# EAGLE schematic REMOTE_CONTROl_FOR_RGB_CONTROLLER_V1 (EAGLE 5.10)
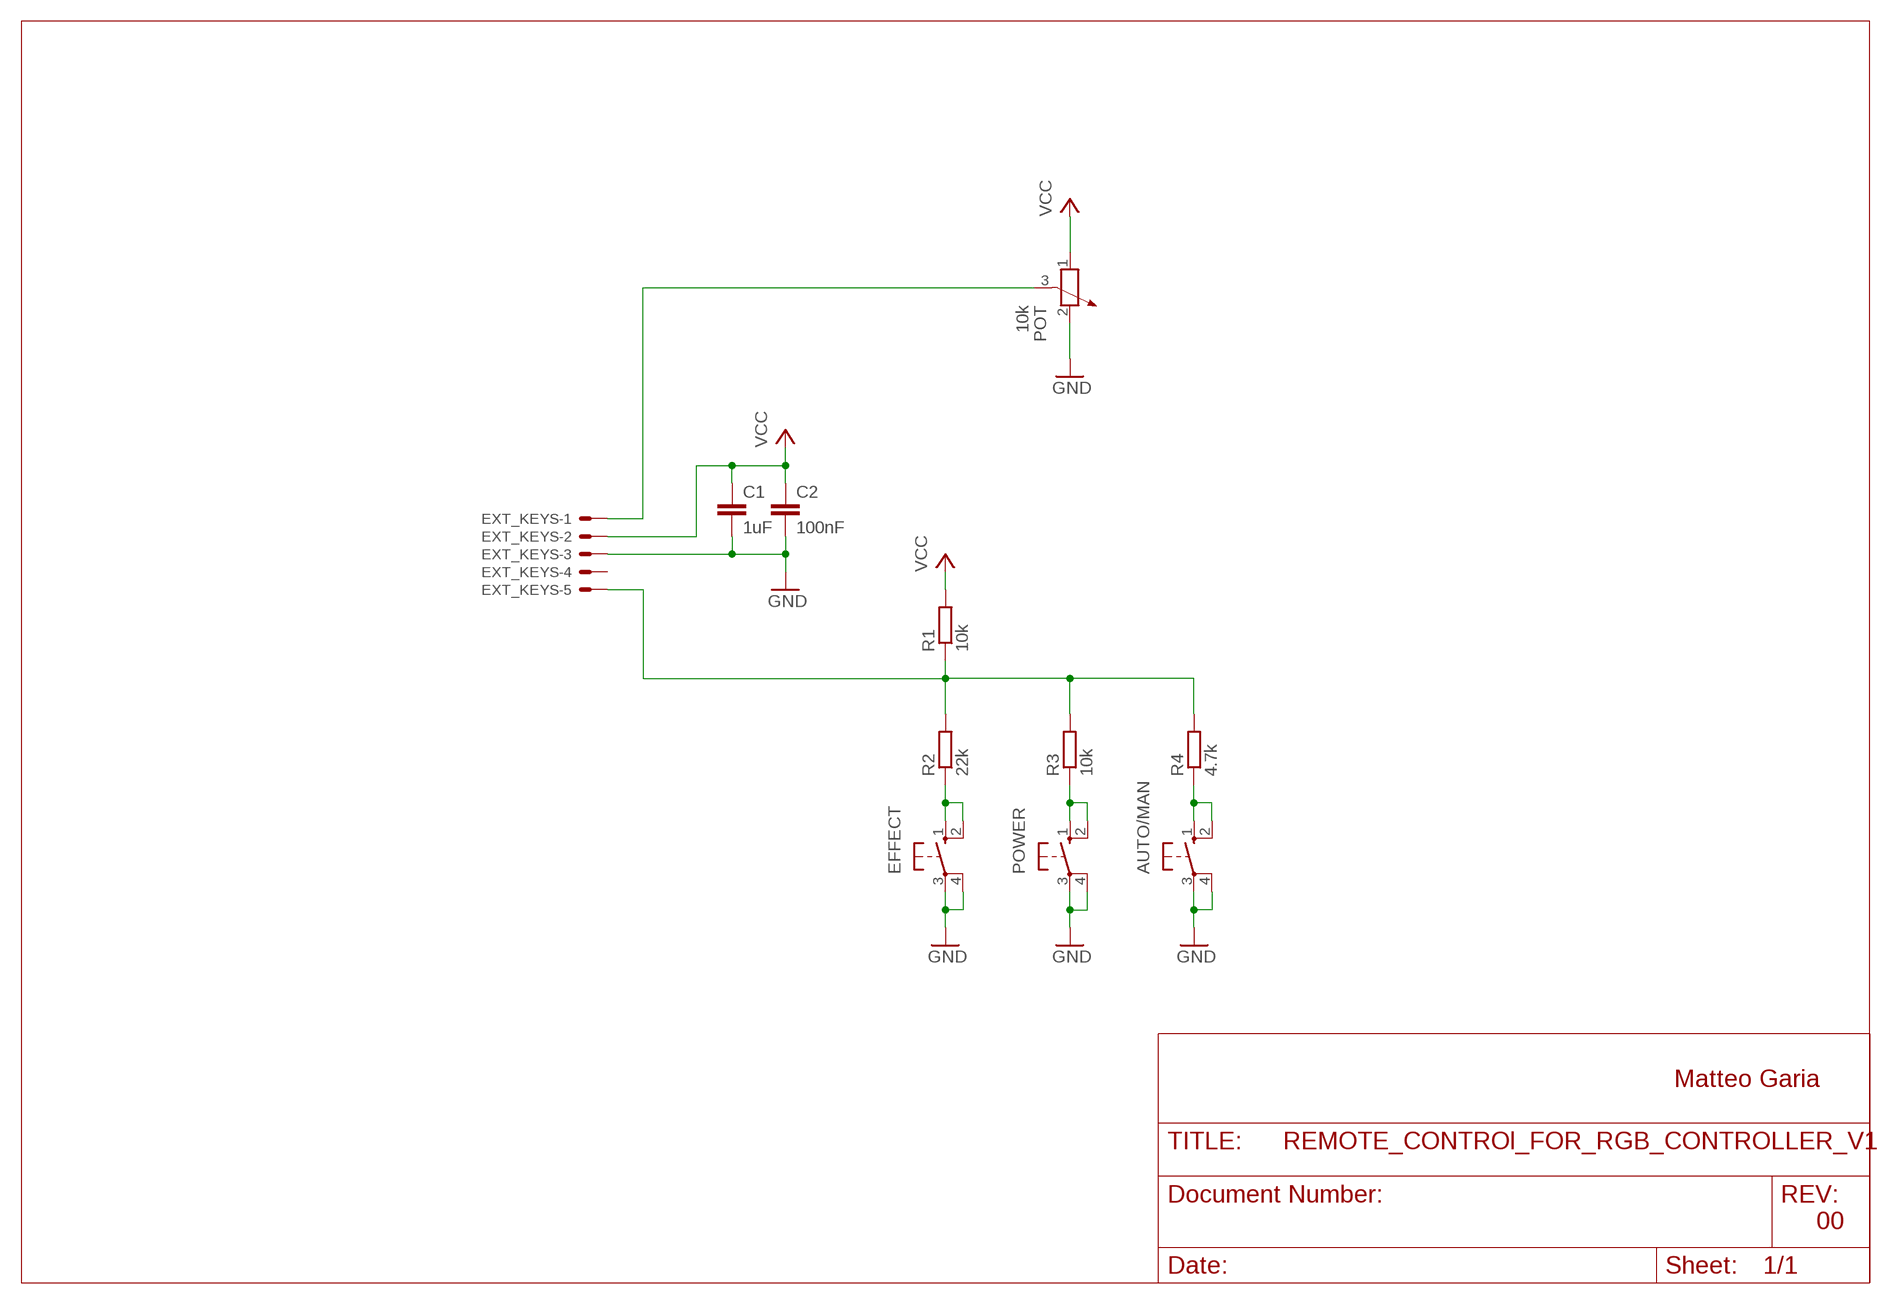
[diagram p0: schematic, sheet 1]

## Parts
AUTO/MAN  10-XX  [B3F-10XX]
C1  1uF  C-EU025-024X044  [C025-024X044]
C2  100nF  C-EU025-024X044  [C025-024X044]
EFFECT  10-XX  [B3F-10XX]
EXT_KEYS  22-23-2051  [22-23-2051]
POT  10k  POTENTIOMETER_PT-10  [PT-10]
POWER  10-XX  [B3F-10XX]
R1  10k  R-EU_0204/7  [0204/7]
R2  22k  R-EU_0204/7  [0204/7]
R3  10k  R-EU_0204/7  [0204/7]
R4  4.7k  R-EU_0204/7  [0204/7]

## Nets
GND: AUTO/MAN.3(P) AUTO/MAN.4(P1) C1.2 C2.2 EFFECT.3(P) EFFECT.4(P1) EXT_KEYS.3 POT.2 POWER.3(P) POWER.4(P1)
N$1: EXT_KEYS.5 R1.1 R2.2 R3.2 R4.2
N$2: EFFECT.1(S) EFFECT.2(S1) R2.1
N$3: EXT_KEYS.1 POT.3
N$4: AUTO/MAN.1(S) AUTO/MAN.2(S1) R4.1
N$8: POWER.1(S) POWER.2(S1) R3.1
VCC: C1.1 C2.1 EXT_KEYS.2 POT.1 R1.2
Unconnected: EXT_KEYS.4

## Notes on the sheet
- Matteo Garia
- 00

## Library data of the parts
AUTO/MAN EFFECT POWER = switch-omron:10-XX: OMRON SWITCH
C1 C2 = rcl:C-EU: CAPACITOR, European symbol
EXT_KEYS = con-molex:22-23-2051: .100" (2.54mm) Center Header - 5 Pin
POT = rcl:POTENTIOMETER_: Potentiometer
R1-R4 = rcl:R-EU_: RESISTOR, European symbol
